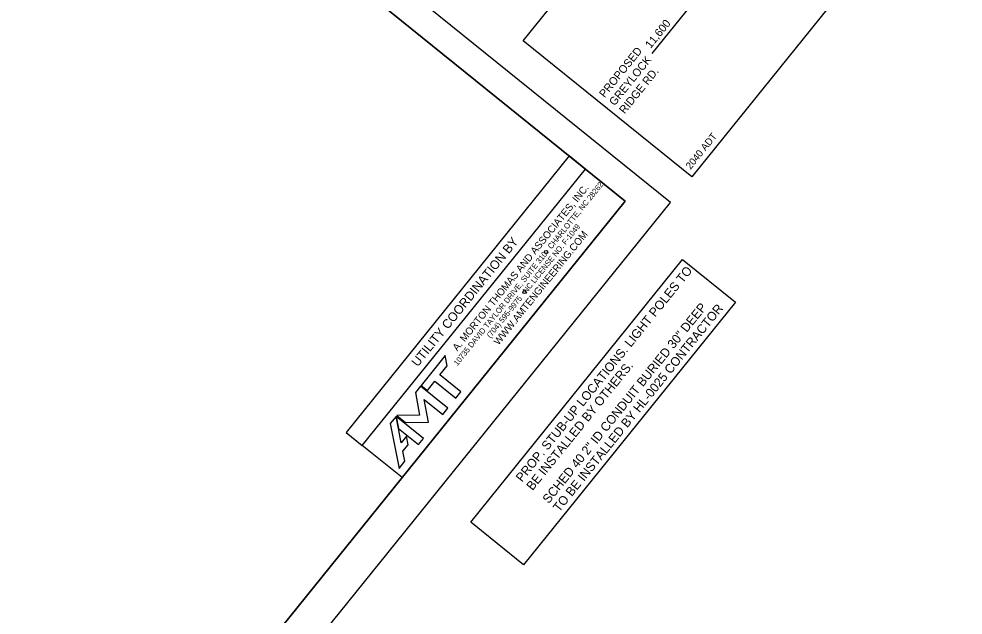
# Model space of a CAD drawing. Extents: x 1487875 to 1489967, y 498345 to 500495.
# Drawn here: x 1489377 to 1489967, y 499398 to 499771 of the extents above; entities that cross this region are included whole.
import ezdxf

# ---------------------------------------------------------------- set-up
doc = ezdxf.new("R2010")
doc.units = 0
for name, color, linetype in [('Exist Utilities Gas UG Line SUE LOS B', 7, 'Continuous'), ('Exist Utilities Sanitary Sewer UG Line', 7, 'Continuous'), ('Exist Utilities Telephone UG FO SUE LOS B', 7, 'Continuous'), ('Exist Utilities TV UG Cable SUE LOS C', 7, 'Continuous'), ('Exist Utilities Water Fire Hydrant CELL', 7, 'Continuous'), ('Exist Utilities Water Meter CELL', 7, 'Continuous'), ('Prop UG Pow Cables', 7, 'Continuous')]:
    doc.layers.add(name, color=color, linetype=linetype)

msp = doc.modelspace()

# ---------------------------------------------------------------- linework, layer by layer
at = {"layer": 'Exist Utilities Sanitary Sewer UG Line'}
msp.add_lwpolyline([(1489591.92, 499503.9), (1489731.31, 499676.74), (1489756.18, 499656.68), (1489616.79, 499483.84)], close=True, dxfattribs=at)
for points in [[(1489653.5, 499537.39), (1489640.33, 499548.01), (1489644.91, 499553.68), (1489643.63, 499560.12), (1489628.63, 499541.53), (1489632.55, 499538.36), (1489637.17, 499544.09), (1489650.34, 499533.47), (1489653.5, 499537.39)], [(1489633.29, 499518.49), (1489630.49, 499532.73), (1489642.16, 499523.32), (1489645.32, 499527.24), (1489628.23, 499541.02), (1489625.07, 499537.1), (1489627.74, 499522.97), (1489613.43, 499522.67), (1489618.87, 499518.28), (1489633.29, 499518.49)], [(1489614.45, 499514.54), (1489613.02, 499522.16), (1489609.33, 499517.59), (1489614.97, 499489.62), (1489618.55, 499494.05), (1489617.28, 499500.33), (1489620.55, 499504.39), (1489619.57, 499509.79), (1489616.19, 499505.59), (1489614.45, 499514.54)], [(1489630.11, 499508.38), (1489613.02, 499522.16), (1489614.45, 499514.54), (1489626.95, 499504.46), (1489630.11, 499508.38)]]:
    msp.add_lwpolyline(points, dxfattribs=at)
for centre in [(1489706.73, 499624.86), (1489693.27, 499599.85)]:
    msp.add_circle(centre, 1, dxfattribs=at)
at = {"layer": 'Exist Utilities Telephone UG FO SUE LOS B'}
msp.add_line((1489773.05, 499749.01), (1489810.55, 499795.51), dxfattribs=at)
at = {"layer": 'Exist Utilities TV UG Cable SUE LOS C'}
for points in [[(1488938.86, 500315.83), (1487997.21, 499148.18), (1488814.55, 498489.05), (1489756.18, 499656.68)], [(1488814.55, 498489.05), (1487997.21, 499148.15), (1488813.25, 500160.1), (1488842.5, 500136.51), (1488968.06, 500292.24), (1489756.18, 499656.68)]]:
    msp.add_lwpolyline(points, close=True, dxfattribs=at)
at = {"layer": 'Exist Utilities Water Fire Hydrant CELL'}
msp.add_lwpolyline([(1488842.5, 500136.51), (1488813.25, 500160.1), (1488087.84, 499260.53), (1488879.09, 498569.08), (1489756.18, 499656.68), (1488968.06, 500292.24)], close=True, dxfattribs=at)
msp.add_lwpolyline([(1488842.5, 500136.51), (1488813.25, 500160.1), (1488087.84, 499260.53), (1488879.09, 498569.08), (1489756.18, 499656.68), (1488968.06, 500292.24)], close=True, dxfattribs=at)
at = {"layer": 'Exist Utilities Water Meter CELL'}
for points in [[(1489692.49, 499756.77), (1489862.05, 499967.03), (1489967.26, 499882.18), (1489797.7, 499671.92)], [(1489591.92, 499503.9), (1489731.31, 499676.74), (1489721.15, 499684.93), (1489581.77, 499512.09)], [(1489591.92, 499503.9), (1489731.31, 499676.74), (1489756.18, 499656.68), (1489616.79, 499483.84)], [(1489659.69, 499456.04), (1489792.03, 499620.14), (1489825.03, 499593.53), (1489692.7, 499429.43)]]:
    msp.add_lwpolyline(points, close=True, dxfattribs=at)
at = {"layer": 'Prop UG Pow Cables'}
msp.add_lwpolyline([(1488727.56, 498345.32), (1489784.38, 499655.78), (1488932.01, 500343.17), (1487875.19, 499032.7)], close=True, dxfattribs=at)

# ---------------------------------------------------------------- texts
at = {"layer": 'Exist Utilities Gas UG Line SUE LOS B'}
for s, p in [('UTILITY COORDINATION BY', (1489626.54, 499552.74)), ('PROP. STUB-UP LOCATIONS. LIGHT POLES TO', (1489691.69, 499480.7)), ('SCHED 40 2" ID CONDUIT BURIED 30" DEEP', (1489708.36, 499467.26)), ('TO BE INSTALLED BY HL-0025 CONTRACTOR', (1489714.93, 499461.96)), ('BE INSTALLED BY OTHERS.', (1489698.26, 499475.4))]:
    msp.add_text(s, height=5.625, rotation=51.11565, dxfattribs=at).set_placement(p)
at = {"layer": 'Exist Utilities Sanitary Sewer UG Line'}
for s, height, p in [('10735 DAVID TAYLOR DRIVE, SUITE 310   CHARLOTTE, NC 28262', 3.5, (1489651.33, 499553.51)), ('A. MORTON THOMAS AND ASSOCIATES, INC.', 4.5, (1489651.31, 499562.64)), ('(704) 595-9975   NC LICENSE NO. F-1049', 3.5, (1489671.98, 499570.75)), ('WWW.AMTENGINEERING.COM', 4.5, (1489677.07, 499566.31))]:
    msp.add_text(s, height=height, rotation=51.11516, dxfattribs=at).set_placement(p)
at = {"layer": 'Exist Utilities Telephone UG FO SUE LOS B'}
for s, height, rotation, p in [('11,600', 5, 51.11565, (1489772.07, 499751.72)), ('PROPOSED', 5, 51.11565, (1489743.29, 499720.93)), ('GREYLOCK', 5, 51.11565, (1489749.54, 499715.88)), ('RIDGE RD.', 5, 51.11565, (1489755.8, 499710.84)), ('2040 ADT', 4.444, 51.12095, (1489797, 499676.18))]:
    msp.add_text(s, height=height, rotation=rotation, dxfattribs=at).set_placement(p)

doc.saveas('drawing.dxf')
